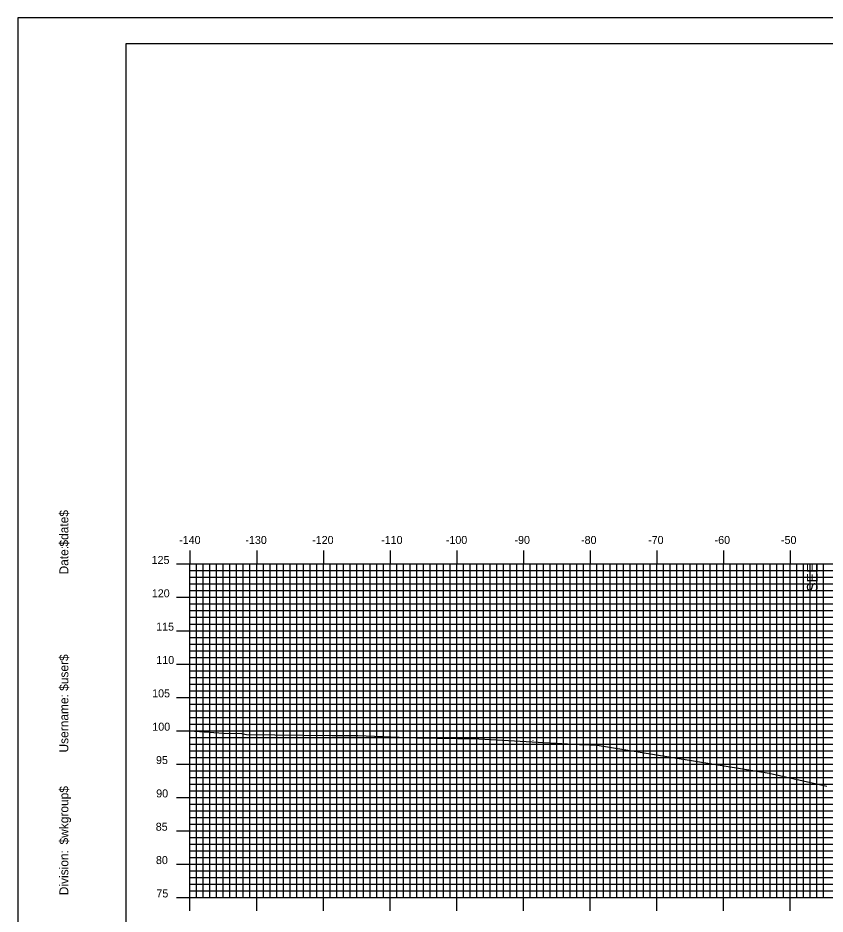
# Model space of a CAD drawing. Extents: x 856084 to 856427, y 364366 to 364586.
# Drawn here: x 856084 to 856205, y 364451.3 to 364585.7 of the extents above; entities that cross this region are included whole.
import ezdxf

# ---------------------------------------------------------------- set-up
doc = ezdxf.new("R2010")
doc.units = 0
for name, color, linetype in [('ANNOTATION', 7, 'Continuous'), ('BORDER', 7, 'Continuous'), ('H_V ANNOTATION', 7, 'Continuous'), ('M_Utilities_Pole', 7, 'Continuous'), ('MAJOR', 7, 'Continuous'), ('MINOR', 7, 'Continuous'), ('PLOT BOUNDARY', 7, 'Continuous'), ('S_Roadway_Centerline', 7, 'Continuous')]:
    doc.layers.add(name, color=color, linetype=linetype)

msp = doc.modelspace()

# ---------------------------------------------------------------- linework, layer by layer
at = {"layer": 'BORDER'}
msp.add_lwpolyline([(856100.2, 364371.79), (856420.2, 364371.79), (856420.2, 364581.79), (856100.2, 364581.79)], close=True, dxfattribs=at)
at = {"layer": 'M_Utilities_Pole'}
msp.add_line((856161.19, 364477.35), (856161.19, 364477.33), dxfattribs=at)
msp.add_circle((856161.19, 364477.34), 0.00417, dxfattribs=at)
at = {"layer": 'MAJOR'}
for p, q in [((856109.8, 364505.79), (856109.8, 364503.79)), ((856119.8, 364505.79), (856119.8, 364503.79)), ((856129.8, 364505.79), (856129.8, 364503.79)), ((856139.8, 364505.79), (856139.8, 364503.79)), ((856149.8, 364505.79), (856149.8, 364503.79)), ((856159.8, 364505.79), (856159.8, 364503.79)), ((856169.8, 364505.79), (856169.8, 364503.79)), ((856179.8, 364505.79), (856179.8, 364503.79)), ((856189.8, 364505.79), (856189.8, 364503.79)), ((856199.8, 364505.79), (856199.8, 364503.79)), ((856107.79, 364503.79), (856109.8, 364503.79)), ((856109.8, 364503.79), (856389.8, 364503.79)), ((856109.8, 364453.79), (856109.8, 364503.79)), ((856109.8, 364453.79), (856109.8, 364503.79)), ((856109.8, 364503.79), (856389.8, 364503.79)), ((856119.8, 364453.79), (856119.8, 364503.79)), ((856129.8, 364453.79), (856129.8, 364503.79)), ((856139.8, 364453.79), (856139.8, 364503.79)), ((856149.8, 364453.79), (856149.8, 364503.79)), ((856159.8, 364453.79), (856159.8, 364503.79)), ((856169.8, 364453.79), (856169.8, 364503.79)), ((856179.8, 364453.79), (856179.8, 364503.79)), ((856189.8, 364453.79), (856189.8, 364503.79)), ((856199.8, 364453.79), (856199.8, 364503.79)), ((856107.79, 364498.79), (856109.8, 364498.79)), ((856109.8, 364498.79), (856389.8, 364498.79)), ((856107.79, 364493.79), (856109.8, 364493.79)), ((856109.8, 364493.79), (856389.8, 364493.79)), ((856107.79, 364488.79), (856109.8, 364488.79)), ((856109.8, 364488.79), (856389.8, 364488.79)), ((856107.79, 364483.79), (856109.8, 364483.79)), ((856109.8, 364483.79), (856389.8, 364483.79)), ((856107.79, 364478.79), (856109.8, 364478.79)), ((856109.8, 364478.79), (856389.8, 364478.79)), ((856107.79, 364473.79), (856109.8, 364473.79)), ((856109.8, 364473.79), (856389.8, 364473.79)), ((856107.79, 364468.79), (856109.8, 364468.79)), ((856109.8, 364468.79), (856389.8, 364468.79)), ((856107.79, 364463.79), (856109.8, 364463.79)), ((856109.8, 364463.79), (856389.8, 364463.79)), ((856107.79, 364458.79), (856109.8, 364458.79)), ((856109.8, 364458.79), (856389.8, 364458.79)), ((856107.79, 364453.79), (856109.8, 364453.79)), ((856109.8, 364453.79), (856389.8, 364453.79)), ((856109.8, 364453.79), (856389.8, 364453.79)), ((856109.8, 364451.78), (856109.8, 364453.79)), ((856119.8, 364451.78), (856119.8, 364453.79)), ((856129.8, 364451.78), (856129.8, 364453.79)), ((856139.8, 364451.78), (856139.8, 364453.79)), ((856149.8, 364451.78), (856149.8, 364453.79)), ((856159.8, 364451.78), (856159.8, 364453.79)), ((856169.8, 364451.78), (856169.8, 364453.79)), ((856179.8, 364451.78), (856179.8, 364453.79)), ((856189.8, 364451.78), (856189.8, 364453.79)), ((856199.8, 364451.78), (856199.8, 364453.79))]:
    msp.add_line(p, q, dxfattribs=at)
at = {"layer": 'MINOR'}
for p, q in [((856110.8, 364453.79), (856110.8, 364503.79)), ((856111.8, 364453.79), (856111.8, 364503.79)), ((856112.8, 364453.79), (856112.8, 364503.79)), ((856113.8, 364453.79), (856113.8, 364503.79)), ((856114.8, 364453.79), (856114.8, 364503.79)), ((856115.8, 364453.79), (856115.8, 364503.79)), ((856116.8, 364453.79), (856116.8, 364503.79)), ((856117.8, 364453.79), (856117.8, 364503.79)), ((856118.8, 364453.79), (856118.8, 364503.79)), ((856120.8, 364453.79), (856120.8, 364503.79)), ((856121.8, 364453.79), (856121.8, 364503.79)), ((856122.8, 364453.79), (856122.8, 364503.79)), ((856123.8, 364453.79), (856123.8, 364503.79)), ((856124.8, 364453.79), (856124.8, 364503.79)), ((856125.8, 364453.79), (856125.8, 364503.79)), ((856126.8, 364453.79), (856126.8, 364503.79)), ((856127.8, 364453.79), (856127.8, 364503.79)), ((856128.8, 364453.79), (856128.8, 364503.79)), ((856130.8, 364453.79), (856130.8, 364503.79)), ((856131.8, 364453.79), (856131.8, 364503.79)), ((856132.8, 364453.79), (856132.8, 364503.79)), ((856133.8, 364453.79), (856133.8, 364503.79)), ((856134.8, 364453.79), (856134.8, 364503.79)), ((856135.8, 364453.79), (856135.8, 364503.79)), ((856136.8, 364453.79), (856136.8, 364503.79)), ((856137.8, 364453.79), (856137.8, 364503.79)), ((856138.8, 364453.79), (856138.8, 364503.79)), ((856140.8, 364453.79), (856140.8, 364503.79)), ((856141.8, 364453.79), (856141.8, 364503.79)), ((856142.8, 364453.79), (856142.8, 364503.79)), ((856143.8, 364453.79), (856143.8, 364503.79)), ((856144.8, 364453.79), (856144.8, 364503.79)), ((856145.8, 364453.79), (856145.8, 364503.79)), ((856146.8, 364453.79), (856146.8, 364503.79)), ((856147.8, 364453.79), (856147.8, 364503.79)), ((856148.8, 364453.79), (856148.8, 364503.79)), ((856150.8, 364453.79), (856150.8, 364503.79)), ((856151.8, 364453.79), (856151.8, 364503.79)), ((856152.8, 364453.79), (856152.8, 364503.79)), ((856153.8, 364453.79), (856153.8, 364503.79)), ((856154.8, 364453.79), (856154.8, 364503.79)), ((856155.8, 364453.79), (856155.8, 364503.79)), ((856156.8, 364453.79), (856156.8, 364503.79)), ((856157.8, 364453.79), (856157.8, 364503.79)), ((856158.8, 364453.79), (856158.8, 364503.79)), ((856160.8, 364453.79), (856160.8, 364503.79)), ((856161.8, 364453.79), (856161.8, 364503.79)), ((856162.8, 364453.79), (856162.8, 364503.79)), ((856163.8, 364453.79), (856163.8, 364503.79)), ((856164.8, 364453.79), (856164.8, 364503.79)), ((856165.8, 364453.79), (856165.8, 364503.79)), ((856166.8, 364453.79), (856166.8, 364503.79)), ((856167.8, 364453.79), (856167.8, 364503.79)), ((856168.8, 364453.79), (856168.8, 364503.79)), ((856170.8, 364453.79), (856170.8, 364503.79)), ((856171.8, 364453.79), (856171.8, 364503.79)), ((856172.8, 364453.79), (856172.8, 364503.79)), ((856173.8, 364453.79), (856173.8, 364503.79)), ((856174.8, 364453.79), (856174.8, 364503.79)), ((856175.8, 364453.79), (856175.8, 364503.79)), ((856176.8, 364453.79), (856176.8, 364503.79)), ((856177.8, 364453.79), (856177.8, 364503.79)), ((856178.8, 364453.79), (856178.8, 364503.79)), ((856180.8, 364453.79), (856180.8, 364503.79)), ((856181.8, 364453.79), (856181.8, 364503.79)), ((856182.8, 364453.79), (856182.8, 364503.79)), ((856183.8, 364453.79), (856183.8, 364503.79)), ((856184.8, 364453.79), (856184.8, 364503.79)), ((856185.8, 364453.79), (856185.8, 364503.79)), ((856186.8, 364453.79), (856186.8, 364503.79)), ((856187.8, 364453.79), (856187.8, 364503.79)), ((856188.8, 364453.79), (856188.8, 364503.79)), ((856190.8, 364453.79), (856190.8, 364503.79)), ((856191.8, 364453.79), (856191.8, 364503.79)), ((856192.8, 364453.79), (856192.8, 364503.79)), ((856193.8, 364453.79), (856193.8, 364503.79)), ((856194.8, 364453.79), (856194.8, 364503.79)), ((856195.8, 364453.79), (856195.8, 364503.79)), ((856196.8, 364453.79), (856196.8, 364503.79)), ((856197.8, 364453.79), (856197.8, 364503.79)), ((856198.8, 364453.79), (856198.8, 364503.79)), ((856200.8, 364453.79), (856200.8, 364503.79)), ((856201.8, 364453.79), (856201.8, 364503.79)), ((856202.8, 364453.79), (856202.8, 364503.79)), ((856203.8, 364453.79), (856203.8, 364503.79)), ((856204.8, 364453.79), (856204.8, 364503.79)), ((856109.8, 364502.79), (856389.8, 364502.79)), ((856109.8, 364502.79), (856111.8, 364502.79)), ((856109.8, 364501.79), (856389.8, 364501.79)), ((856109.8, 364501.79), (856111.8, 364501.79)), ((856109.8, 364500.79), (856389.8, 364500.79)), ((856109.8, 364500.79), (856111.8, 364500.79)), ((856109.8, 364499.79), (856389.8, 364499.79)), ((856109.8, 364499.79), (856111.8, 364499.79)), ((856109.8, 364497.79), (856389.8, 364497.79)), ((856109.8, 364497.79), (856111.8, 364497.79)), ((856109.8, 364496.79), (856389.8, 364496.79)), ((856109.8, 364496.79), (856111.8, 364496.79)), ((856109.8, 364495.79), (856389.8, 364495.79)), ((856109.8, 364495.79), (856111.8, 364495.79)), ((856109.8, 364494.79), (856389.8, 364494.79)), ((856109.8, 364494.79), (856111.8, 364494.79)), ((856109.8, 364492.79), (856389.8, 364492.79)), ((856109.8, 364492.79), (856111.8, 364492.79)), ((856109.8, 364491.79), (856389.8, 364491.79)), ((856109.8, 364491.79), (856111.8, 364491.79)), ((856109.8, 364490.79), (856389.8, 364490.79)), ((856109.8, 364490.79), (856111.8, 364490.79)), ((856109.8, 364489.79), (856389.8, 364489.79)), ((856109.8, 364489.79), (856111.8, 364489.79)), ((856109.8, 364487.79), (856389.8, 364487.79)), ((856109.8, 364487.79), (856111.8, 364487.79)), ((856109.8, 364486.79), (856389.8, 364486.79)), ((856109.8, 364486.79), (856111.8, 364486.79)), ((856109.8, 364485.79), (856389.8, 364485.79)), ((856109.8, 364485.79), (856111.8, 364485.79)), ((856109.8, 364484.79), (856389.8, 364484.79)), ((856109.8, 364484.79), (856111.8, 364484.79)), ((856109.8, 364482.79), (856389.8, 364482.79)), ((856109.8, 364482.79), (856111.8, 364482.79)), ((856109.8, 364481.79), (856389.8, 364481.79)), ((856109.8, 364481.79), (856111.8, 364481.79)), ((856109.8, 364480.79), (856389.8, 364480.79)), ((856109.8, 364480.79), (856111.8, 364480.79)), ((856109.8, 364479.79), (856389.8, 364479.79)), ((856109.8, 364479.79), (856111.8, 364479.79)), ((856109.8, 364477.79), (856389.8, 364477.79)), ((856109.8, 364477.79), (856111.8, 364477.79)), ((856109.8, 364476.79), (856389.8, 364476.79)), ((856109.8, 364476.79), (856111.8, 364476.79)), ((856109.8, 364475.79), (856389.8, 364475.79)), ((856109.8, 364475.79), (856111.8, 364475.79)), ((856109.8, 364474.79), (856389.8, 364474.79)), ((856109.8, 364474.79), (856111.8, 364474.79)), ((856109.8, 364472.79), (856389.8, 364472.79)), ((856109.8, 364472.79), (856111.8, 364472.79)), ((856109.8, 364471.79), (856389.8, 364471.79)), ((856109.8, 364471.79), (856111.8, 364471.79)), ((856109.8, 364470.79), (856389.8, 364470.79)), ((856109.8, 364470.79), (856111.8, 364470.79)), ((856109.8, 364469.79), (856389.8, 364469.79)), ((856109.8, 364469.79), (856111.8, 364469.79)), ((856109.8, 364467.79), (856389.8, 364467.79)), ((856109.8, 364467.79), (856111.8, 364467.79)), ((856109.8, 364466.79), (856389.8, 364466.79)), ((856109.8, 364466.79), (856111.8, 364466.79)), ((856109.8, 364465.79), (856389.8, 364465.79)), ((856109.8, 364465.79), (856111.8, 364465.79)), ((856109.8, 364464.79), (856389.8, 364464.79)), ((856109.8, 364464.79), (856111.8, 364464.79)), ((856109.8, 364462.79), (856389.8, 364462.79)), ((856109.8, 364462.79), (856111.8, 364462.79)), ((856109.8, 364461.79), (856389.8, 364461.79)), ((856109.8, 364461.79), (856111.8, 364461.79)), ((856109.8, 364460.79), (856389.8, 364460.79)), ((856109.8, 364460.79), (856111.8, 364460.79)), ((856109.8, 364459.79), (856389.8, 364459.79)), ((856109.8, 364459.79), (856111.8, 364459.79)), ((856109.8, 364457.79), (856389.8, 364457.79)), ((856109.8, 364457.79), (856111.8, 364457.79)), ((856109.8, 364456.79), (856389.8, 364456.79)), ((856109.8, 364456.79), (856111.8, 364456.79)), ((856109.8, 364455.79), (856389.8, 364455.79)), ((856109.8, 364455.79), (856111.8, 364455.79)), ((856109.8, 364454.79), (856389.8, 364454.79)), ((856109.8, 364454.79), (856111.8, 364454.79))]:
    msp.add_line(p, q, dxfattribs=at)
at = {"layer": 'PLOT BOUNDARY'}
msp.add_lwpolyline([(856084.01, 364365.67), (856424.01, 364365.67), (856424.01, 364585.67), (856084.01, 364585.67)], close=True, dxfattribs=at)
at = {"layer": 'S_Roadway_Centerline'}
msp.add_lwpolyline([(856109.8, 364478.75), (856114.82, 364478.42), (856117.58, 364478.36), (856118.27, 364478.21), (856131.05, 364478.05), (856134.99, 364478.05), (856143.64, 364477.7), (856153.12, 364477.59), (856168.19, 364476.73), (856169.88, 364476.66), (856170.85, 364476.6), (856196.61, 364472.4), (856205.25, 364470.46)], dxfattribs=at)

# ---------------------------------------------------------------- texts
at = {"layer": 'ANNOTATION'}
msp.add_text('SEE', height=1.6, rotation=90, dxfattribs=at).set_placement((856203.89, 364499.59))
at = {"layer": 'BORDER'}
for s, p in [('$date$', (856091.57, 364506.4)), ('Date:', (856091.57, 364502.22)), ('$user$', (856091.57, 364484.77)), ('Username:', (856091.57, 364475.52)), ('$wkgroup$', (856091.57, 364461.73)), ('Division:', (856091.57, 364454.12))]:
    msp.add_text(s, height=1.339, rotation=90, dxfattribs=at).set_placement(p)
at = {"layer": 'H_V ANNOTATION'}
for s, p in [('-140', (856108.18, 364506.79)), ('-130', (856118.11, 364506.79)), ('-120', (856128.12, 364506.79)), ('-110', (856138.46, 364506.79)), ('-100', (856148.16, 364506.79)), ('-90', (856158.45, 364506.79)), ('-80', (856168.43, 364506.79)), ('-70', (856178.48, 364506.79)), ('-60', (856188.45, 364506.79)), ('-50', (856198.4, 364506.79)), ('125', (856104.05, 364503.79)), ('120', (856104.08, 364498.79)), ('115', (856104.73, 364493.79)), ('110', (856104.76, 364488.79)), ('105', (856104.13, 364483.79)), ('100', (856104.16, 364478.79)), ('95', (856104.71, 364473.79)), ('90', (856104.74, 364468.79)), ('85', (856104.67, 364463.79)), ('80', (856104.7, 364458.79)), ('75', (856104.77, 364453.79))]:
    msp.add_text(s, height=1.2, dxfattribs=at).set_placement(p)
at = {"layer": 'MAJOR'}
msp.add_text('-', height=0.012, dxfattribs=at).set_placement((856109.79, 364453.79))

doc.saveas('drawing.dxf')
